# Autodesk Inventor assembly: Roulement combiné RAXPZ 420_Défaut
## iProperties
Shininess: 64.0
Length Units: 11269
Angle Units: 11279
Time Units: 11290
Mass Units: 11283
Length Display Precision: 3
Angle Display Precision: 2
Compacted: True
Created: 2006-01
Part Number: Roulement combiné RAXPZ 420_Défaut
Document SubType Name: Assembly
Designer: riri
Density: 0.0
Volumn: 0.0
Area: 0.0
PropertySet Name: Model Information
Control State: 0
Master: False
Checked Out: False
Author: riri
